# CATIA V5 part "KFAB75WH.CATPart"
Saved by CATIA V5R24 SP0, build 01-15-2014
Part number: KFAB75
Bounding box of the stored display mesh (mm): x 0 to 511.438, y -340.415 to 409.585, z -239.647 to 260.995
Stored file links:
  \\sr02\Apell\Disegni\DISEGNI\SMEG\CAPPE\KFAB75BL\Assiemi\BIM\KFAB75BL.CATPart
  \\sr02\Apell\Disegni\DISEGNI\PARTI\2601777\2601777A_BIM.CATPart
  \\sr02\Apell\Disegni\DISEGNI\PARTI\1700886\1700886_BIM.CATPart
  \\sr02\Apell\Disegni\DISEGNI\PARTI\1800037\1800037_BIM.CATPart
  \\sr02\Apell\Disegni\DISEGNI\PARTI\2610222\2610222_BIM.CATPart
  \\sr02\Apell\Disegni\DISEGNI\PARTI\2601833\2601833_BIM.CATPart
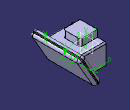
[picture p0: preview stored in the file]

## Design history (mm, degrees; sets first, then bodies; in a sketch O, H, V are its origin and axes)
Solid1 "1700886": linked copy from another document
Solid2 "2601777A": linked copy from another document
Solid3 "1700886": linked copy from another document
Solid4 "1800037": linked copy from another document
Solid5 "1800037": linked copy from another document
Solid6 "2610222": linked copy from another document
Solid7 "2601833": linked copy from another document
Body1 (main body)
Body2 "Box"
Body3 "Guscio"
Body4 "Guscio"
Body5 "Faretto"
Body6 "Faretto"
Body7 "Filtro"
Body8 "Cappuccio"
